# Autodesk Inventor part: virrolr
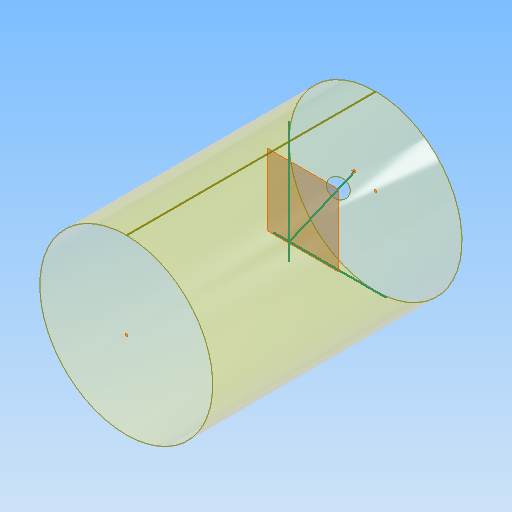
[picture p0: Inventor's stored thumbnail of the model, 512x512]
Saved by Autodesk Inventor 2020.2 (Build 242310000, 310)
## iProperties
Created: 2020-04
Part Number: virrolr
Material: Acier
Document SubType Name: Tôle
Designer: t.sancier
Density: 7.85 g/cm^3
Flat Pattern Width: 230 cm
Flat Pattern Length: 500.702 cm
Flat Pattern Area: 115161 cm^2
Sheet Metal Rule: Par défaut_mm
Sheet Metal Width: 2300,000 mm
Sheet Metal Length: 5007,018 mm
Sheet Metal Area: 11516141,426 mm^2
Appearance: Transparent - Jaune
Author: t.sancier
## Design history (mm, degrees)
feature "Profil roulé1" dims "d1" = 359.5 deg, "d2" = 4 (= Epaisseur), "d4" = 5007.01801, "d5" = 798
extrude "Extrusion2" cut sketch "Esquisse ouverture1" stored distance "d8" = 10; taper "d9" = 0 deg
chamfer "Chanfrein1" distance "d10" = 2; stored, may be unused: second distance "d11" = 2, angle "d12" = 45 deg
node "Solide1"
feature "Définition1"
other parameters: "Epaisseur" = 4 (derived), "FacteurX" = 4.4, "RayonPli" = 4 (= Epaisseur), "LargeurGrugeage" = 4 (= Epaisseur), "ProfondeurGrugeage" = 2 (= 0.5 x Epaisseur), "TailleGrugeage" = 16 (= 4 x Epaisseur), "JeuJointure" = 0.01, "RestesMinimum" = 8 (= 2 x Epaisseur), "Rayondetransition" = 4 (= RayonPli), "TailleRayonJacobi" = 4 (= RayonPli), "TailleJeu" = 4 (= Epaisseur), "d3" = 4 (= RayonPli), "Epaisseur" = 4, "LargeurGrugeage" = 4, "ProfondeurGrugeage" = 2, "RayonPli" = 4, "Rayondetransition" = 4, "RestesMinimum" = 8, "TailleGrugeage" = 16, "TailleJeu" = 4, "TailleRayonJacobi" = 4
